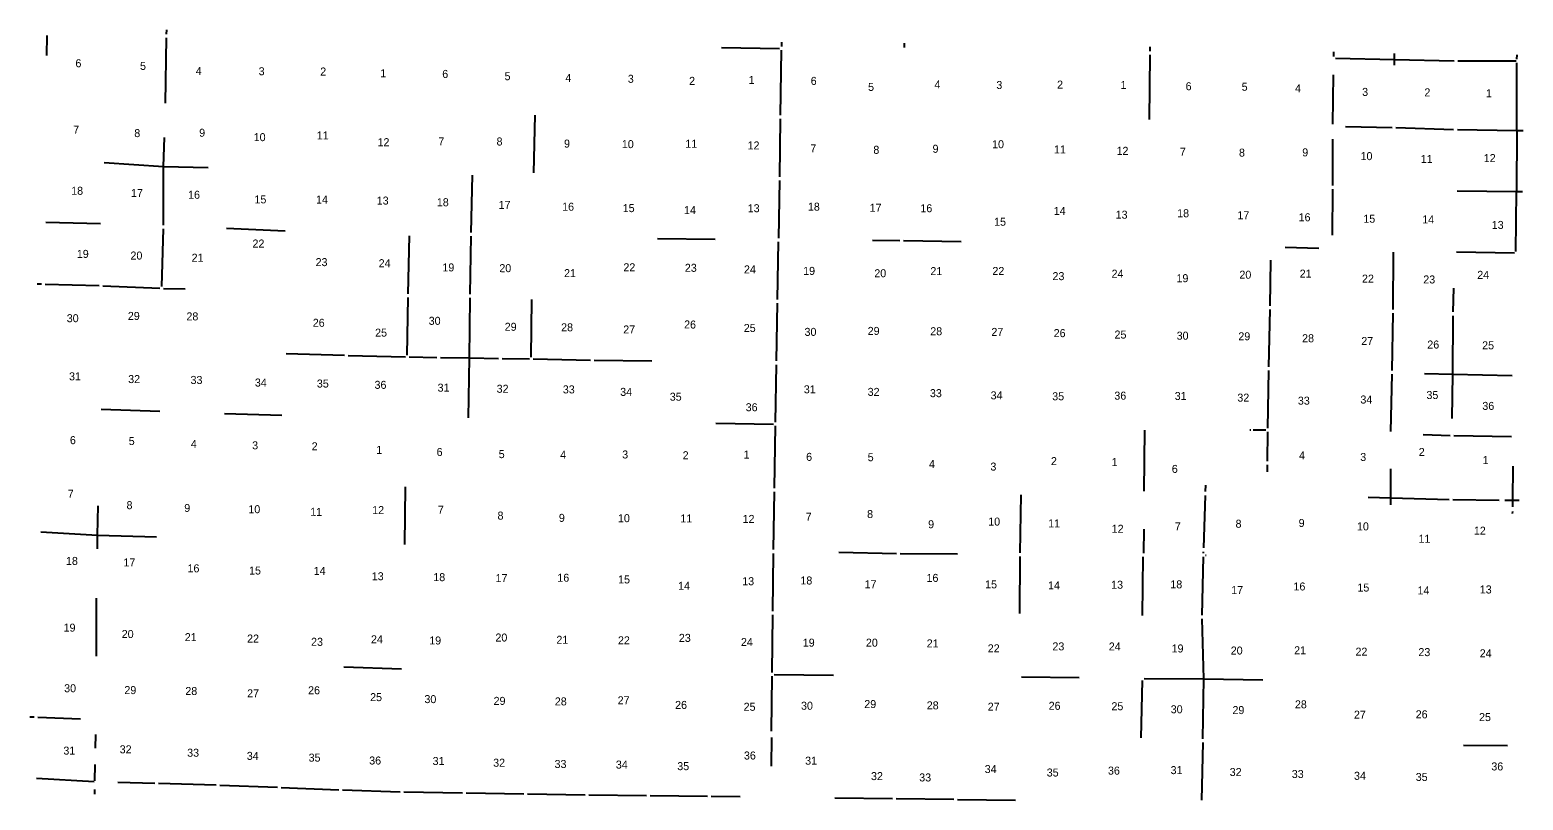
# Model space of a CAD drawing. Extents: x -2933025 to 31692252, y -2344676 to 23854604.
# Drawn here: x -2646615 to -2518535, y -2270535 to -2204460 of the extents above; entities that cross this region are included whole.
import ezdxf

# ---------------------------------------------------------------- set-up
doc = ezdxf.new("R2010")
doc.units = 0
doc.layers.add('tdCoSectLinePart', color=7, linetype='Continuous')
doc.layers.add('tdCoSectNmbr', color=7, linetype='Continuous')

msp = doc.modelspace()

# ---------------------------------------------------------------- linework, layer by layer
at = {"layer": 'tdCoSectLinePart'}
for points in [[(-2645163, -2206651), (-2645135, -2204948)], [(-2634981, -2210755), (-2634889, -2205147)], [(-2634884, -2204831), (-2634878, -2204460)], [(-2582148, -2205523), (-2582153, -2205893)], [(-2587285, -2205968), (-2582314, -2206048)], [(-2582245, -2211786), (-2582158, -2206209)], [(-2571595, -2205973), (-2571590, -2205598)], [(-2550590, -2212146), (-2550522, -2206598)], [(-2550517, -2206282), (-2550511, -2205912)], [(-2534770, -2206736), (-2534764, -2206358)], [(-2529569, -2207005), (-2529567, -2206477)], [(-2519062, -2206961), (-2519057, -2206592)], [(-2534620, -2206889), (-2529569, -2207005)], [(-2529572, -2207500), (-2529569, -2207005)], [(-2529569, -2207005), (-2524463, -2207108)], [(-2524146, -2207111), (-2519133, -2207119)], [(-2519062, -2213085), (-2519064, -2207278)], [(-2534845, -2212556), (-2534790, -2208316)], [(-2603377, -2216735), (-2603282, -2211773)], [(-2582250, -2212102), (-2582321, -2217057)], [(-2533780, -2212740), (-2529760, -2212837)], [(-2529444, -2212846), (-2524495, -2213012)], [(-2524178, -2213020), (-2519062, -2213085)], [(-2519062, -2213085), (-2519106, -2218320)], [(-2519062, -2213085), (-2518535, -2213090)], [(-2635149, -2216170), (-2635071, -2213690)], [(-2534863, -2217812), (-2534851, -2213842)], [(-2640237, -2215831), (-2635149, -2216170)], [(-2635149, -2216170), (-2631328, -2216269)], [(-2635146, -2221201), (-2635149, -2216170)], [(-2608750, -2221854), (-2608649, -2216912)], [(-2582326, -2217374), (-2582410, -2222332)], [(-2534894, -2222060), (-2534864, -2218129)], [(-2524198, -2218262), (-2519106, -2218320)], [(-2519150, -2223471), (-2519106, -2218320)], [(-2519106, -2218320), (-2518579, -2218327)], [(-2645232, -2220963), (-2640552, -2221067)], [(-2635294, -2226479), (-2635151, -2221517)], [(-2629744, -2221470), (-2624728, -2221692)], [(-2614154, -2227093), (-2614066, -2222140)], [(-2608835, -2227142), (-2608756, -2222171)], [(-2592770, -2222369), (-2587845, -2222421)], [(-2582497, -2227597), (-2582415, -2222649)], [(-2574329, -2222505), (-2572005, -2222527)], [(-2571688, -2222532), (-2566746, -2222624)], [(-2538933, -2223102), (-2536061, -2223195)], [(-2540237, -2228124), (-2540186, -2224204)], [(-2529690, -2228438), (-2529650, -2223519)], [(-2524237, -2223493), (-2519278, -2223594)], [(-2645997, -2226243), (-2645627, -2226252)], [(-2645311, -2226261), (-2640662, -2226398)], [(-2640345, -2226410), (-2635456, -2226630)], [(-2635140, -2226641), (-2633283, -2226689)], [(-2524524, -2228661), (-2524473, -2226617)], [(-2614247, -2232359), (-2614160, -2227412)], [(-2608900, -2232599), (-2608839, -2227459)], [(-2603603, -2232528), (-2603548, -2227579)], [(-2582579, -2232865), (-2582502, -2227915)], [(-2540334, -2233352), (-2540242, -2228441)], [(-2529773, -2233688), (-2529694, -2228755)], [(-2524570, -2234006), (-2524529, -2228980)], [(-2624637, -2232230), (-2619619, -2232371)], [(-2619303, -2232380), (-2614409, -2232513)], [(-2614092, -2232520), (-2611702, -2232556)], [(-2611385, -2232561), (-2608900, -2232599)], [(-2608986, -2237732), (-2608900, -2232599)], [(-2608900, -2232599), (-2606416, -2232640)], [(-2606099, -2232646), (-2603763, -2232684)], [(-2603447, -2232689), (-2598524, -2232784)], [(-2598207, -2232790), (-2593264, -2232862)], [(-2582660, -2238118), (-2582584, -2233181)], [(-2540437, -2238619), (-2540340, -2233669)], [(-2529891, -2238921), (-2529780, -2234005)], [(-2526999, -2233932), (-2524570, -2234006)], [(-2524618, -2237787), (-2524570, -2234006)], [(-2524570, -2234006), (-2519468, -2234113)], [(-2640500, -2236994), (-2635470, -2237158)], [(-2629923, -2237361), (-2624995, -2237509)], [(-2587776, -2238211), (-2582821, -2238274)], [(-2582744, -2243770), (-2582665, -2238435)], [(-2551030, -2244035), (-2550968, -2238791)], [(-2541989, -2238756), (-2541880, -2238757)], [(-2541698, -2238760), (-2540598, -2238775)], [(-2540458, -2241450), (-2540441, -2238935)], [(-2527122, -2239177), (-2524795, -2239259)], [(-2524478, -2239266), (-2519530, -2239328)], [(-2540465, -2242372), (-2540461, -2241767)], [(-2529884, -2244595), (-2529889, -2242127)], [(-2519413, -2244805), (-2519390, -2241879)], [(-2614453, -2248596), (-2614390, -2243652)], [(-2545769, -2244073), (-2545762, -2243510)], [(-2582828, -2249048), (-2582749, -2244087)], [(-2561663, -2249307), (-2561576, -2244351)], [(-2545928, -2248890), (-2545776, -2244389)], [(-2531825, -2244539), (-2529884, -2244595)], [(-2529896, -2245211), (-2529884, -2244595)], [(-2529884, -2244595), (-2524872, -2244733)], [(-2524555, -2244740), (-2520584, -2244790)], [(-2520115, -2244796), (-2519413, -2244805)], [(-2519423, -2245364), (-2519413, -2244805)], [(-2519413, -2244805), (-2518885, -2244816)], [(-2640803, -2247799), (-2640768, -2245301)], [(-2519433, -2245935), (-2519430, -2245774)], [(-2645670, -2247522), (-2640803, -2247799)], [(-2640827, -2248968), (-2640803, -2247799)], [(-2640803, -2247799), (-2635751, -2247940)], [(-2551079, -2247300), (-2551109, -2249340)], [(-2582875, -2254312), (-2582832, -2249365)], [(-2577235, -2249253), (-2572278, -2249377)], [(-2571959, -2249381), (-2567047, -2249400)], [(-2561691, -2254515), (-2561666, -2249623)], [(-2551172, -2254689), (-2551113, -2249657)], [(-2546056, -2254657), (-2545952, -2249677)], [(-2545943, -2249361), (-2545939, -2249227)], [(-2545790, -2249523), (-2545714, -2249525)], [(-2640912, -2258180), (-2640912, -2253218)], [(-2582938, -2259585), (-2582878, -2254629)], [(-2545909, -2260117), (-2546055, -2254973)], [(-2619685, -2259089), (-2614739, -2259267)], [(-2582998, -2264622), (-2582942, -2259901)], [(-2582782, -2259745), (-2577699, -2259803)], [(-2561559, -2259958), (-2556614, -2260022)], [(-2551296, -2265205), (-2551175, -2260259)], [(-2551032, -2260113), (-2545909, -2260117)], [(-2545995, -2265275), (-2545909, -2260117)], [(-2545909, -2260117), (-2540867, -2260227)], [(-2646615, -2263386), (-2646245, -2263395)], [(-2645929, -2263405), (-2642258, -2263565)], [(-2640979, -2266091), (-2640958, -2264895)], [(-2583005, -2265173), (-2583035, -2267616)], [(-2546001, -2265591), (-2546109, -2270529)], [(-2523638, -2265816), (-2519869, -2265855)], [(-2641028, -2268875), (-2641003, -2267465)], [(-2646037, -2268651), (-2641086, -2268935)], [(-2639069, -2268994), (-2635903, -2269083)], [(-2635586, -2269092), (-2630649, -2269234)], [(-2630333, -2269245), (-2625378, -2269437)], [(-2625061, -2269450), (-2620119, -2269653)], [(-2641037, -2270013), (-2641034, -2269637)], [(-2619803, -2269665), (-2614858, -2269813)], [(-2614544, -2269820), (-2609506, -2269915)], [(-2609189, -2269921), (-2604250, -2270000)], [(-2603933, -2270005), (-2598999, -2270088)], [(-2598683, -2270092), (-2593721, -2270148)], [(-2593404, -2270151), (-2588483, -2270201)], [(-2588166, -2270204), (-2585694, -2270233)], [(-2577582, -2270337), (-2572633, -2270403)], [(-2572316, -2270407), (-2567364, -2270465)], [(-2567047, -2270468), (-2562084, -2270535)]]:
    msp.add_lwpolyline(points, dxfattribs=at)

# ---------------------------------------------------------------- texts
at = {"layer": 'tdCoSectNmbr'}
for s, height, rotation, p in [('6', 686, 359.94467, (-2642706, -2207668)), ('5', 686, 359.94547, (-2637165, -2207894)), ('4', 686, 359.94616, (-2632384, -2208321)), ('3', 686, 359.94694, (-2626993, -2208354)), ('2', 686, 359.94771, (-2621709, -2208375)), ('1', 686, 359.94844, (-2616560, -2208524)), ('6', 686, 359.94922, (-2611244, -2208583)), ('5', 686, 359.94999, (-2605900, -2208777)), ('4', 686, 359.95151, (-2600688, -2208922)), ('3', 686, 359.95229, (-2595328, -2209000)), ('2', 686, 359.95305, (-2590070, -2209178)), ('1', 686, 359.95378, (-2584964, -2209095)), ('6', 686, 359.95456, (-2579641, -2209181)), ('5', 686, 359.95527, (-2574719, -2209696)), ('4', 686, 359.9561, (-2569024, -2209488)), ('3', 686, 359.95686, (-2563718, -2209531)), ('2', 686, 359.95762, (-2558505, -2209496)), ('1', 686, 359.9584, (-2553068, -2209527)), ('6', 686, 359.95921, (-2547484, -2209639)), ('5', 686, 359.95991, (-2542676, -2209683)), ('4', 686, 359.96057, (-2538097, -2209814)), ('3', 686, 359.96103, (-2532342, -2210125)), ('2', 686, 359.9618, (-2527002, -2210165)), ('1', 686, 359.96256, (-2521720, -2210242)), ('7', 686, 359.94466, (-2642894, -2213361)), ('8', 686, 359.94542, (-2637659, -2213659)), ('9', 686, 359.94622, (-2632095, -2213629)), ('11', 686.4, 359.94769, (-2622005, -2213857)), ('10', 686.4, 359.94692, (-2627417, -2214007)), ('12', 686.4, 359.94846, (-2616794, -2214439)), ('7', 686, 359.94919, (-2611582, -2214375)), ('8', 686, 359.94991, (-2606586, -2214379)), ('9', 686, 359.95148, (-2600799, -2214558)), ('10', 686.4, 359.95222, (-2595840, -2214606)), ('11', 686.4, 359.953, (-2590399, -2214570)), ('12', 686.4, 359.95378, (-2585055, -2214716)), ('7', 686, 359.95453, (-2579677, -2214970)), ('8', 686, 359.95532, (-2574267, -2215093)), ('9', 686, 359.95605, (-2569189, -2215003)), ('10', 686.4, 359.95681, (-2564083, -2214614)), ('11', 686.4, 359.95757, (-2558778, -2215063)), ('12', 686.4, 359.95836, (-2553409, -2215180)), ('7', 686, 359.95912, (-2547978, -2215261)), ('8', 686, 359.95986, (-2542908, -2215333)), ('9', 686, 359.96064, (-2537479, -2215312)), ('10', 686.4, 359.96102, (-2532481, -2215635)), ('11', 686.4, 359.96176, (-2527316, -2215872)), ('12', 686.4, 359.96255, (-2521916, -2215803)), ('18', 686.4, 359.94467, (-2643072, -2218606)), ('17', 686.4, 359.94541, (-2637940, -2218798)), ('16', 686.4, 359.94612, (-2633045, -2218948)), ('15', 686.4, 359.94694, (-2627351, -2219344)), ('14', 686.4, 359.94771, (-2622068, -2219358)), ('13', 686.4, 359.94846, (-2616864, -2219446)), ('18', 686.4, 359.94921, (-2611709, -2219590)), ('17', 686.4, 359.94997, (-2606406, -2219813)), ('16', 686.4, 359.95146, (-2600960, -2219974)), ('15', 686.4, 359.95221, (-2595765, -2220093)), ('14', 686.4, 359.95296, (-2590508, -2220263)), ('13', 686.4, 359.95376, (-2585044, -2220105)), ('18', 686.4, 359.95451, (-2579880, -2219972)), ('17', 686.4, 359.95527, (-2574588, -2220068)), ('16', 686.4, 359.95597, (-2570234, -2220106)), ('15', 686.4, 359.95682, (-2563911, -2221262)), ('14', 686.4, 359.95756, (-2558792, -2220327)), ('13', 686.4, 359.95832, (-2553486, -2220658)), ('18', 686.4, 359.95909, (-2548209, -2220533)), ('17', 686.4, 359.95984, (-2543041, -2220700)), ('16', 686.4, 359.96059, (-2537792, -2220877)), ('15', 686.4, 359.96099, (-2532239, -2221002)), ('14', 686.4, 359.96178, (-2527192, -2221068)), ('13', 686.4, 359.96265, (-2521229, -2221536)), ('19', 686.4, 359.94476, (-2642586, -2224019)), ('20', 686.4, 359.94542, (-2637985, -2224164)), ('22', 686.4, 359.94694, (-2627519, -2223133)), ('21', 686.4, 359.94617, (-2632742, -2224348)), ('23', 686.4, 359.94772, (-2622107, -2224727)), ('24', 686.4, 359.9485, (-2616699, -2224820)), ('19', 686.4, 359.94929, (-2611232, -2225179)), ('20', 686.4, 359.95, (-2606348, -2225245)), ('22', 686.4, 359.9522, (-2595706, -2225167)), ('23', 686.4, 359.95296, (-2590437, -2225214)), ('24', 686.4, 359.95369, (-2585366, -2225349)), ('21', 686.4, 359.95145, (-2600796, -2225672)), ('19', 686.4, 359.95443, (-2580287, -2225477)), ('20', 686.4, 359.95531, (-2574186, -2225680)), ('21', 686.4, 359.956, (-2569378, -2225501)), ('22', 686.4, 359.95678, (-2564057, -2225483)), ('23', 686.4, 359.95752, (-2558903, -2225928)), ('24', 686.4, 359.95826, (-2553836, -2225722)), ('19', 686.4, 359.95906, (-2548268, -2226103)), ('20', 686.4, 359.95984, (-2542871, -2225805)), ('21', 686.4, 359.96058, (-2537700, -2225713)), ('22', 686.4, 359.96103, (-2532356, -2226143)), ('23', 686.4, 359.96179, (-2527099, -2226213)), ('24', 686.4, 359.96246, (-2522470, -2225818)), ('30', 686.4, 359.94465, (-2643451, -2229538)), ('29', 686.4, 359.9454, (-2638211, -2229343)), ('28', 686.4, 359.94613, (-2633185, -2229383)), ('26', 686.4, 359.9477, (-2622349, -2229930)), ('30', 686.4, 359.94931, (-2612407, -2229760)), ('29', 686.4, 359.95008, (-2605888, -2230272)), ('28', 686.4, 359.95141, (-2601048, -2230317)), ('27', 686.4, 359.95218, (-2595719, -2230503)), ('26', 686.4, 358.95293, (-2590505, -2230068)), ('25', 686.4, 359.95367, (-2585381, -2230374)), ('25', 686.4, 359.94847, (-2617001, -2230774)), ('30', 686.4, 359.95443, (-2580170, -2230710)), ('29', 686.4, 359.95521, (-2574754, -2230628)), ('28', 686.4, 359.95599, (-2569387, -2230656)), ('27', 686.4, 359.95674, (-2564142, -2230714)), ('26', 686.4, 359.95752, (-2558802, -2230819)), ('25', 686.4, 359.95827, (-2553582, -2230940)), ('30', 686.4, 359.95904, (-2548254, -2231036)), ('29', 686.4, 359.95981, (-2542960, -2231087)), ('28', 686.4, 359.9606, (-2537492, -2231256)), ('27', 686.4, 359.96102, (-2532417, -2231493)), ('26', 686.4, 359.96184, (-2526755, -2231796)), ('25', 686.4, 359.96252, (-2522049, -2231861)), ('31', 686.4, 359.94469, (-2643255, -2234526)), ('32', 686.4, 359.94543, (-2638182, -2234758)), ('33', 686.4, 359.9462, (-2632832, -2234834)), ('34', 686.4, 359.947, (-2627315, -2235057)), ('35', 686.4, 359.94776, (-2621999, -2235142)), ('36', 686.4, 359.94848, (-2617051, -2235252)), ('31', 686.4, 359.94926, (-2611644, -2235497)), ('32', 686.4, 359.94999, (-2606580, -2235589)), ('33', 686.4, 359.95141, (-2600902, -2235645)), ('31', 686.4, 359.95439, (-2580233, -2235637)), ('34', 686.4, 359.95212, (-2595980, -2235858)), ('35', 686.4, 359.95273, (-2591730, -2236273)), ('32', 686.4, 359.95519, (-2574756, -2235858)), ('33', 686.4, 359.95596, (-2569416, -2235966)), ('34', 686.4, 359.95671, (-2564210, -2236156)), ('35', 686.4, 359.95748, (-2558927, -2236235)), ('36', 686.4, 359.95825, (-2553599, -2236181)), ('31', 686.4, 359.95899, (-2548421, -2236207)), ('32', 686.4, 359.95977, (-2543047, -2236351)), ('33', 686.4, 359.96052, (-2537855, -2236610)), ('34', 686.4, 359.96101, (-2532492, -2236513)), ('35', 686.4, 359.96183, (-2526828, -2236126)), ('36', 686.4, 359.95368, (-2585218, -2237175)), ('36', 686.4, 359.96252, (-2522035, -2237060)), ('6', 686, 359.9447, (-2643180, -2240000)), ('5', 686, 359.94543, (-2638135, -2240075)), ('4', 686, 359.9462, (-2632808, -2240325)), ('3', 686, 359.94696, (-2627548, -2240443)), ('2', 686, 359.94769, (-2622444, -2240522)), ('1', 686, 359.94849, (-2616909, -2240832)), ('6', 686, 359.94924, (-2611726, -2241010)), ('5', 686, 359.95001, (-2606400, -2241198)), ('4', 686, 359.95134, (-2601129, -2241250)), ('3', 686, 359.95211, (-2595809, -2241225)), ('2', 686, 359.95286, (-2590624, -2241290)), ('1', 686, 359.95361, (-2585397, -2241232)), ('6', 686, 359.95439, (-2580032, -2241431)), ('5', 686, 359.95515, (-2574752, -2241461)), ('4', 686, 359.95591, (-2569498, -2242047)), ('2', 686, 359.95742, (-2559037, -2241793)), ('1', 686, 359.95817, (-2553830, -2241877)), ('4', 686, 359.9605, (-2537754, -2241304)), ('3', 686, 359.96098, (-2532506, -2241439)), ('2', 686, 359.96174, (-2527487, -2241013)), ('1', 686, 359.96249, (-2522009, -2241705)), ('3', 686, 359.95667, (-2564226, -2242265)), ('6', 686, 359.95894, (-2548668, -2242466)), ('7', 686, 359.94469, (-2643366, -2244602)), ('8', 686, 359.94542, (-2638323, -2245575)), ('9', 686, 359.94613, (-2633373, -2245816)), ('10', 686.4, 359.94695, (-2627874, -2245923)), ('11', 686.4, 359.94771, (-2622573, -2246147)), ('12', 686.4, 359.94848, (-2617254, -2245997)), ('7', 686, 359.94928, (-2611622, -2245972)), ('8', 686, 359.95001, (-2606503, -2246469)), ('9', 686, 359.9513, (-2601241, -2246665)), ('10', 686.4, 359.95206, (-2596171, -2246691)), ('11', 686.4, 359.95282, (-2590823, -2246712)), ('12', 686.4, 359.9536, (-2585483, -2246756)), ('7', 686, 359.95436, (-2580071, -2246571)), ('8', 686, 359.95513, (-2574804, -2246337)), ('9', 686, 359.95588, (-2569568, -2247213)), ('10', 686.4, 359.95664, (-2564415, -2246985)), ('11', 686.4, 359.95738, (-2559274, -2247140)), ('8', 686, 359.95969, (-2543201, -2247169)), ('9', 686, 359.96047, (-2537788, -2247099)), ('12', 686.4, 359.95817, (-2553826, -2247599)), ('7', 686, 359.95894, (-2548405, -2247389)), ('10', 686.4, 359.96096, (-2532786, -2247395)), ('11', 686.4, 359.96171, (-2527509, -2248455)), ('12', 686.4, 359.96246, (-2522761, -2247764)), ('18', 686.4, 359.9447, (-2643517, -2250359)), ('17', 686.4, 359.94542, (-2638588, -2250487)), ('16', 686.4, 359.94621, (-2633093, -2250992)), ('15', 686.4, 359.94697, (-2627813, -2251181)), ('14', 686.4, 359.94778, (-2622269, -2251209)), ('13', 686.4, 359.94849, (-2617291, -2251672)), ('18', 686.4, 359.94926, (-2612012, -2251751)), ('17', 686.4, 359.95003, (-2606676, -2251836)), ('16', 686.4, 359.95129, (-2601372, -2251799)), ('15', 686.4, 359.95204, (-2596161, -2251946)), ('13', 686.4, 359.95358, (-2585515, -2252099)), ('18', 686.4, 359.9543, (-2580526, -2252037)), ('16', 686.4, 359.95586, (-2569707, -2251814)), ('14', 686.4, 359.95278, (-2591015, -2252493)), ('17', 686.4, 359.95509, (-2575019, -2252359)), ('15', 686.4, 359.95659, (-2564681, -2252367)), ('14', 686.4, 359.95737, (-2559284, -2252454)), ('13', 686.4, 359.95815, (-2553873, -2252401)), ('18', 686.4, 359.95888, (-2548795, -2252368)), ('17', 686.4, 359.95963, (-2543575, -2252864)), ('16', 686.4, 359.96041, (-2538234, -2252548)), ('15', 686.4, 359.96096, (-2532749, -2252641)), ('14', 686.4, 359.9617, (-2527594, -2252887)), ('13', 686.4, 359.96248, (-2522255, -2252807)), ('19', 686.4, 359.94469, (-2643721, -2256081)), ('20', 686.4, 359.94543, (-2638735, -2256628)), ('21', 686.4, 359.94618, (-2633331, -2256897)), ('22', 686.4, 359.94696, (-2627981, -2257017)), ('23', 686.4, 359.94776, (-2622495, -2257296)), ('24', 686.4, 359.9485, (-2617359, -2257081)), ('19', 686.4, 359.94922, (-2612361, -2257183)), ('20', 686.4, 359.95004, (-2606683, -2256929)), ('21', 686.4, 359.95125, (-2601454, -2257125)), ('22', 686.4, 359.95202, (-2596175, -2257169)), ('23', 686.4, 359.95278, (-2590948, -2256959)), ('24', 686.4, 359.95354, (-2585625, -2257313)), ('19', 686.4, 359.95431, (-2580321, -2257368)), ('20', 686.4, 359.95509, (-2574907, -2257371)), ('21', 686.4, 359.95584, (-2569690, -2257433)), ('22', 686.4, 359.9566, (-2564456, -2257858)), ('23', 686.4, 359.9574, (-2558909, -2257690)), ('24', 686.4, 359.9581, (-2554076, -2257698)), ('19', 686.4, 359.95887, (-2548686, -2257867)), ('20', 686.4, 359.95961, (-2543613, -2258046)), ('21', 686.4, 359.96039, (-2538176, -2258023)), ('22', 686.4, 359.96093, (-2532914, -2258144)), ('23', 686.4, 359.96171, (-2527519, -2258181)), ('24', 686.4, 359.96247, (-2522260, -2258284)), ('30', 686.4, 359.94471, (-2643675, -2261280)), ('29', 686.4, 359.94546, (-2638509, -2261438)), ('28', 686.4, 359.94621, (-2633281, -2261517)), ('27', 686.4, 359.94698, (-2627979, -2261717)), ('26', 686.4, 359.94773, (-2622750, -2261454)), ('25', 686.4, 359.9485, (-2617431, -2262042)), ('30', 686.4, 359.94918, (-2612774, -2262212)), ('29', 686.4, 359.95003, (-2606840, -2262364)), ('28', 686.4, 359.95122, (-2601588, -2262410)), ('27', 686.4, 359.952, (-2596201, -2262312)), ('26', 686.4, 359.95271, (-2591271, -2262710)), ('25', 686.4, 359.95356, (-2585396, -2262868)), ('30', 686.4, 359.95427, (-2580471, -2262781)), ('29', 686.4, 359.95505, (-2575046, -2262637)), ('28', 686.4, 359.95583, (-2569687, -2262748)), ('27', 686.4, 359.95658, (-2564457, -2262863)), ('26', 686.4, 359.95733, (-2559232, -2262786)), ('25', 686.4, 359.95811, (-2553847, -2262823)), ('30', 686.4, 359.95885, (-2548761, -2263083)), ('29', 686.4, 359.95961, (-2543468, -2263154)), ('28', 686.4, 359.96039, (-2538110, -2262660)), ('27', 686.4, 359.96091, (-2533048, -2263547)), ('26', 686.4, 359.96167, (-2527751, -2263517)), ('25', 686.4, 359.96246, (-2522316, -2263753)), ('31', 686.4, 359.94473, (-2643740, -2266629)), ('32', 686.4, 359.94543, (-2638912, -2266521)), ('33', 686.4, 359.94627, (-2633124, -2266812)), ('34', 686.4, 359.94701, (-2628009, -2267081)), ('35', 686.4, 359.94778, (-2622705, -2267231)), ('36', 686.4, 359.94853, (-2617509, -2267480)), ('31', 686.4, 359.9493, (-2612071, -2267523)), ('32', 686.4, 359.95006, (-2606877, -2267669)), ('36', 686.4, 359.95356, (-2585368, -2267050)), ('31', 686.4, 359.95432, (-2580117, -2267494)), ('33', 686.4, 359.95123, (-2601611, -2267776)), ('34', 686.4, 359.95199, (-2596353, -2267828)), ('35', 686.4, 359.95274, (-2591087, -2267962)), ('32', 686.4, 359.95514, (-2574469, -2268817)), ('33', 686.4, 359.95567, (-2570333, -2268931)), ('34', 686.4, 359.95655, (-2564718, -2268213)), ('35', 686.4, 359.95732, (-2559397, -2268508)), ('36', 686.4, 359.95808, (-2554146, -2268345)), ('31', 686.4, 359.95884, (-2548772, -2268304)), ('32', 686.4, 359.95958, (-2543704, -2268468)), ('33', 686.4, 359.96035, (-2538378, -2268638)), ('34', 686.4, 359.96082, (-2533042, -2268790)), ('35', 686.4, 359.96159, (-2527747, -2268888)), ('36', 686.4, 359.96245, (-2521263, -2267987))]:
    msp.add_text(s, height=height, rotation=rotation, dxfattribs=at).set_placement(p)

doc.saveas('drawing.dxf')
